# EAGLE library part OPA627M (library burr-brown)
Difet(R) Operational Amplifiers Precision, High-Speed
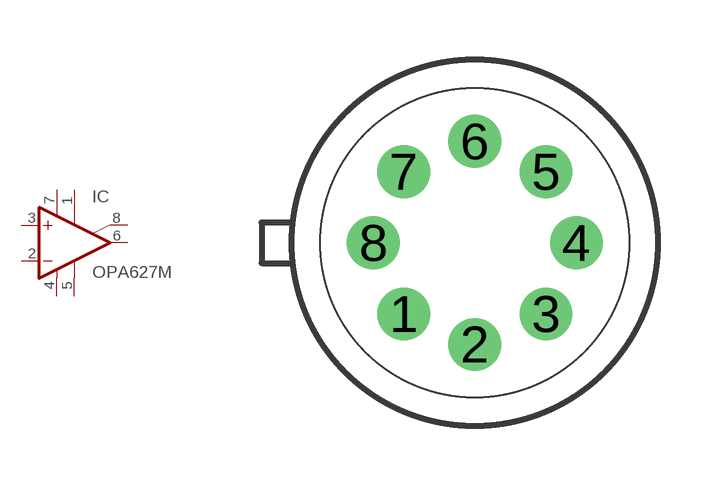
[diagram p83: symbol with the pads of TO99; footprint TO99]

Designator prefix IC

## OPA627M (MF: TEXAS INSTRUMENT CONNECTORS; MPN: OPA627AM; OC_FARNELL: 1459637; OC_NEWARK: 72K7290)  [TO99]
1  TRIM1  pas
2  -IN  in
3  +IN  in
4  V-  pwr
5  TRIM2  pas
6  OUT  out
7  V+  pwr
8  CASE  pas

## Footprint TO99 (pad centres in mm)
Metal can Package
drill 0.813 round: 1 -1.778,-1.778; 2 0,-2.54; 3 1.778,-1.778; 4 2.54,0; 5 1.778,1.778; 6 0,2.54; 7 -1.778,1.778; 8 -2.54,0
